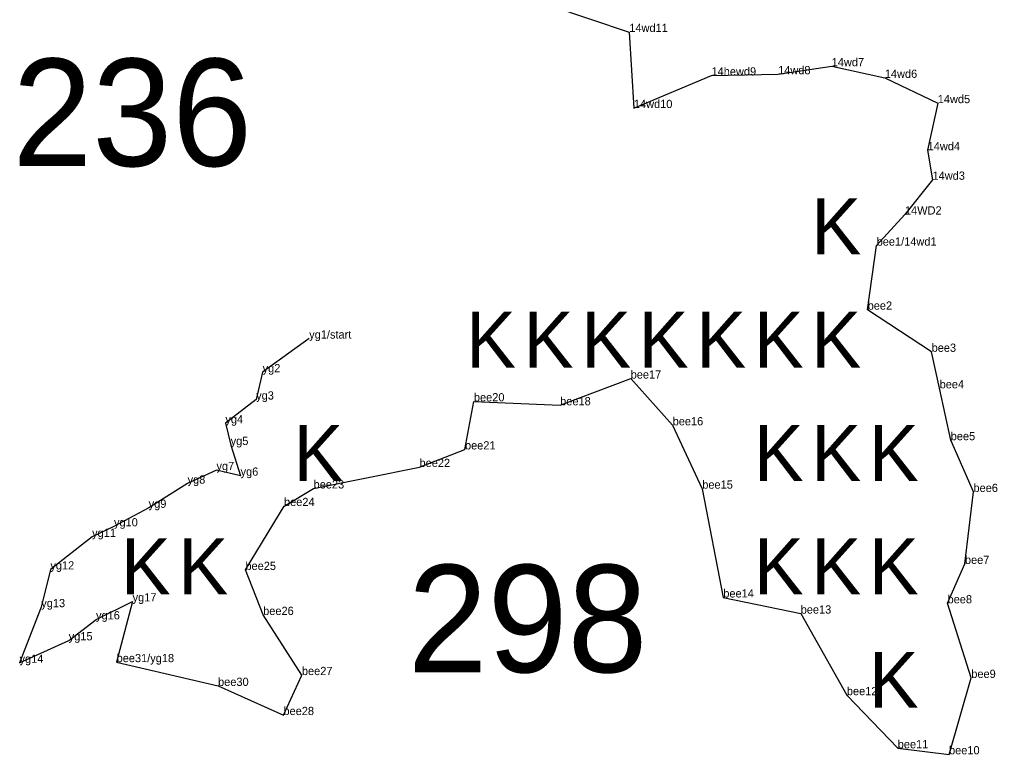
# Model space of a CAD drawing. Extents: x 2072529 to 2268812, y 436423 to 470008.
# Drawn here: x 2256757 to 2257352, y 441160 to 441607 of the extents above; entities that cross this region are included whole.
import ezdxf

# ---------------------------------------------------------------- set-up
doc = ezdxf.new("R2010")
doc.units = 0
for name, color, linetype in [('Old_Level_20', 7, 'Continuous'), ('Old_Level_52', 7, 'Continuous'), ('Old_Level_55', 7, 'Continuous'), ('Old_Level_60', 7, 'Continuous'), ('Old_Level_62', 7, 'Continuous')]:
    doc.layers.add(name, color=color, linetype=linetype)

msp = doc.modelspace()

# ---------------------------------------------------------------- linework, layer by layer
at = {"layer": 'Old_Level_20'}
for p, q in [((2257127.888, 441599.821), (2257127.888, 441599.821)), ((2257250.977, 441578.994), (2257250.977, 441578.994)), ((2257177.892, 441573.359), (2257177.892, 441573.359)), ((2257218.413, 441574.116), (2257218.413, 441574.116)), ((2257283.293, 441571.913), (2257283.293, 441571.913)), ((2257130.676, 441553.562), (2257130.676, 441553.562)), ((2257315.501, 441556.531), (2257315.501, 441556.531)), ((2257309.351, 441527.841), (2257309.351, 441527.841)), ((2257312.312, 441509.907), (2257312.312, 441509.907)), ((2257295.548, 441488.76), (2257295.548, 441488.76)), ((2257278.335, 441469.816), (2257278.335, 441469.816)), ((2257272.862, 441430.855), (2257272.862, 441430.855)), ((2256933.169, 441413.269), (2256933.169, 441413.269)), ((2257311.779, 441405.231), (2257311.779, 441405.231)), ((2256904.844, 441392.772), (2256904.844, 441392.772)), ((2257128.72, 441388.918), (2257128.72, 441388.918)), ((2257316.645, 441382.995), (2257316.645, 441382.995)), ((2256900.918, 441376.167), (2256900.918, 441376.167)), ((2257033.362, 441375.059), (2257033.362, 441375.059)), ((2257085.831, 441372.693), (2257085.831, 441372.693)), ((2256882.21, 441361.715), (2256882.21, 441361.715)), ((2257154.253, 441360.486), (2257154.253, 441360.486)), ((2257323.391, 441351.433), (2257323.391, 441351.433)), ((2256885.415, 441348.49), (2256885.415, 441348.49)), ((2257027.937, 441345.805), (2257027.937, 441345.805)), ((2256876.778, 441333.229), (2256876.778, 441333.229)), ((2257000.285, 441335.125), (2257000.285, 441335.125)), ((2256891.444, 441329.82), (2256891.444, 441329.82)), ((2256859.194, 441325.009), (2256859.194, 441325.009)), ((2256935.845, 441322.052), (2256935.845, 441322.052)), ((2257172.268, 441321.927), (2257172.268, 441321.927)), ((2257337.23, 441319.92), (2257337.23, 441319.92)), ((2256835.533, 441310.294), (2256835.533, 441310.294)), ((2256917.858, 441311.368), (2256917.858, 441311.368)), ((2256814.432, 441299.004), (2256814.432, 441299.004)), ((2256801.108, 441292.571), (2256801.108, 441292.571)), ((2256775.741, 441272.765), (2256775.741, 441272.765)), ((2256894.388, 441272.478), (2256894.388, 441272.478)), ((2257332.021, 441276.15), (2257332.021, 441276.15)), ((2257185.051, 441255.731), (2257185.051, 441255.731)), ((2256770.218, 441249.81), (2256770.218, 441249.81)), ((2256825.747, 441253.297), (2256825.747, 441253.297)), ((2257321.468, 441252.175), (2257321.468, 441252.175)), ((2256803.516, 441242.392), (2256803.516, 441242.392)), ((2256905.17, 441245.102), (2256905.17, 441245.102)), ((2257232.132, 441245.904), (2257232.132, 441245.904)), ((2256786.901, 441229.625), (2256786.901, 441229.625)), ((2256757, 441215.969), (2256757, 441215.969)), ((2256816.045, 441216.367), (2256816.045, 441216.367)), ((2256928.737, 441208.504), (2256928.737, 441208.504)), ((2257335.897, 441206.768), (2257335.897, 441206.768)), ((2256877.754, 441201.91), (2256877.754, 441201.91)), ((2257260.215, 441196.265), (2257260.215, 441196.265)), ((2256917.523, 441184.175), (2256917.523, 441184.175)), ((2257291.167, 441163.968), (2257291.167, 441163.968)), ((2257322.367, 441160.28), (2257322.367, 441160.28))]:
    msp.add_line(p, q, dxfattribs=at)
at = {"layer": 'Old_Level_52'}
for points in [[(2257079.647, 441615.883), (2257127.888, 441599.821), (2257130.676, 441553.562), (2257177.892, 441573.359), (2257218.413, 441574.116), (2257250.977, 441578.994), (2257283.293, 441571.913), (2257315.501, 441556.531), (2257309.351, 441527.841), (2257312.312, 441509.907)], [(2257312.312, 441509.907), (2257295.548, 441488.76), (2257278.335, 441469.816)], [(2256933.169, 441413.269), (2256904.844, 441392.772), (2256900.918, 441376.167), (2256882.21, 441361.715), (2256885.415, 441348.49), (2256891.444, 441329.82), (2256876.778, 441333.229), (2256859.194, 441325.009), (2256835.533, 441310.294), (2256814.432, 441299.004), (2256801.108, 441292.571), (2256775.741, 441272.765), (2256770.218, 441249.81), (2256757, 441215.969), (2256786.901, 441229.625), (2256803.516, 441242.392), (2256825.747, 441253.297), (2256816.045, 441216.367), (2256877.754, 441201.91), (2256917.523, 441184.175), (2256928.737, 441208.504), (2256905.17, 441245.102), (2256894.388, 441272.478), (2256917.858, 441311.368), (2256935.845, 441322.052), (2257000.285, 441335.125), (2257027.937, 441345.805), (2257033.362, 441375.059), (2257085.831, 441372.693), (2257128.72, 441388.918), (2257154.253, 441360.486), (2257172.268, 441321.927), (2257185.051, 441255.731), (2257232.132, 441245.904), (2257260.215, 441196.265), (2257291.167, 441163.968), (2257322.367, 441160.28), (2257335.897, 441206.768), (2257321.468, 441252.175), (2257332.021, 441276.15), (2257337.23, 441319.92), (2257323.391, 441351.433), (2257316.645, 441382.995), (2257311.779, 441405.231), (2257272.862, 441430.855), (2257278.335, 441469.816)]]:
    msp.add_lwpolyline(points, dxfattribs=at)

# ---------------------------------------------------------------- texts
at = {"layer": 'Old_Level_55'}
for p in [(2257238.589, 441464.631), (2257028.589, 441395.631), (2257063.589, 441395.631), (2257098.589, 441395.631), (2257133.589, 441395.631), (2257168.589, 441395.631), (2257203.589, 441395.631), (2257238.589, 441395.631), (2256923.589, 441326.631), (2257203.589, 441326.631), (2257238.589, 441326.631), (2257273.589, 441326.631), (2256818.589, 441257.631), (2256853.589, 441257.631), (2257203.589, 441257.631), (2257238.589, 441257.631), (2257273.589, 441257.631), (2257273.589, 441188.631)]:
    msp.add_text('K', height=34, dxfattribs=at).set_placement(p)
at = {"layer": 'Old_Level_60'}
for s, p in [('14wd11', (2257127.888, 441599.821)), ('14wd7', (2257250.977, 441578.994)), ('14hewd9', (2257177.892, 441573.359)), ('14wd8', (2257218.413, 441574.116)), ('14wd6', (2257283.293, 441571.913)), ('14wd10', (2257130.676, 441553.562)), ('14wd5', (2257315.501, 441556.531)), ('14wd4', (2257309.351, 441527.841)), ('14wd3', (2257312.312, 441509.907)), ('14WD2', (2257295.548, 441488.76)), ('bee1/14wd1', (2257278.335, 441469.816)), ('bee2', (2257272.862, 441430.855)), ('yg1/start', (2256933.169, 441413.269)), ('bee3', (2257311.779, 441405.231)), ('yg2', (2256904.844, 441392.772)), ('bee17', (2257128.72, 441388.918)), ('bee4', (2257316.645, 441382.995)), ('yg3', (2256900.918, 441376.167)), ('bee20', (2257033.362, 441375.059)), ('bee18', (2257085.831, 441372.693)), ('yg4', (2256882.21, 441361.715)), ('bee16', (2257154.253, 441360.486)), ('bee5', (2257323.391, 441351.433)), ('yg5', (2256885.415, 441348.49)), ('bee21', (2257027.937, 441345.805)), ('yg7', (2256876.778, 441333.229)), ('bee22', (2257000.285, 441335.125)), ('yg6', (2256891.444, 441329.82)), ('yg8', (2256859.194, 441325.009)), ('bee23', (2256935.845, 441322.052)), ('bee15', (2257172.268, 441321.927)), ('bee6', (2257337.23, 441319.92)), ('yg9', (2256835.533, 441310.294)), ('bee24', (2256917.858, 441311.368)), ('yg10', (2256814.432, 441299.004)), ('yg11', (2256801.108, 441292.571)), ('yg12', (2256775.741, 441272.765)), ('bee7', (2257332.021, 441276.15)), ('bee25', (2256894.388, 441272.478)), ('bee14', (2257185.051, 441255.731)), ('yg13', (2256770.218, 441249.81)), ('yg17', (2256825.747, 441253.297)), ('bee8', (2257321.468, 441252.175)), ('bee26', (2256905.17, 441245.102)), ('bee13', (2257232.132, 441245.904)), ('yg16', (2256803.516, 441242.392)), ('yg15', (2256786.901, 441229.625)), ('yg14', (2256757, 441215.969)), ('bee31/yg18', (2256816.045, 441216.367)), ('bee27', (2256928.737, 441208.504)), ('bee30', (2256877.754, 441201.91)), ('bee9', (2257335.897, 441206.768)), ('bee12', (2257260.215, 441196.265)), ('bee28', (2256917.523, 441184.175)), ('bee11', (2257291.167, 441163.968)), ('bee10', (2257322.367, 441160.28))]:
    msp.add_text(s, height=5, dxfattribs=at).set_placement(p)
at = {"layer": 'Old_Level_62'}
for s, p in [('236', (2256752.66, 441518.24)), ('298', (2256993.14, 441210.231))]:
    msp.add_text(s, height=65.34, dxfattribs=at).set_placement(p)

doc.saveas('drawing.dxf')
